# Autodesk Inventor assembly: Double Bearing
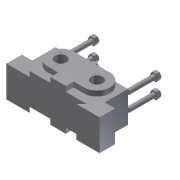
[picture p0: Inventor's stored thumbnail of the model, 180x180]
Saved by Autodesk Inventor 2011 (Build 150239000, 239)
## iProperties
Created: 2009-05
Part Number: Double Bearing
Document SubType Name: Assembly
Designer: Sham
Author: Sham
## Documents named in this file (5)
- C:\Inventor_2011\c10_inv_2010_05042010\Double Bearing\Double Bearing.iam
- C:\Inventor_2011\c10_inv_2010_05042010\Double Bearing\base.ipt
- C:\Inventor_2011\c10_inv_2010_05042010\Double Bearing\cap.ipt
- C:\Inventor_2011\c10_inv_2010_05042010\Double Bearing\bolt.ipt
- C:\Inventor_2011\c10_inv_2010_05042010\Double Bearing\bushing.ipt
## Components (10 placed, 4 different names)
1. base:1 — Mate:1, Mate:2, Mate:3, Insert:3, Insert:4
2. cap:1 — Mate:1, Mate:2, Mate:3, Insert:1, Insert:2
3. bushing:2 — Insert:3
4. bushing:3 — Insert:4
5. bolt:1 — Insert:1
6. bolt:6
7. bolt:7
8. bolt:8
9. bolt:5 — Insert:2
10. bolt:9
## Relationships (7: Insert 4, Mate 3)
- Mate:1: base:1 ↔ cap:1
- Mate:2: base:1 ↔ cap:1
- Mate:3: base:1 ↔ cap:1
- Insert:1: cap:1 ↔ bolt:1
- Insert:2: cap:1 ↔ bolt:5
- Insert:3: base:1 ↔ bushing:2
- Insert:4: base:1 ↔ bushing:3
